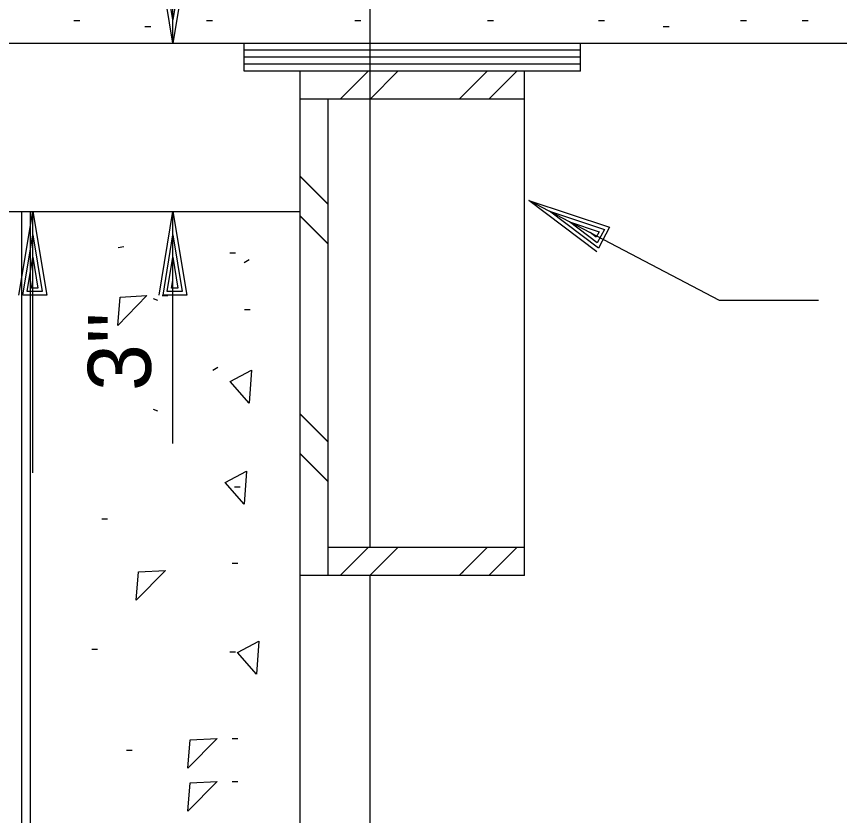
# Model space of a CAD drawing. Extents: x 22388.1 to 22405.7, y 22369.6 to 22390.4.
# Drawn here: x 22396.418 to 22397.03, y 22375.768 to 22376.362 of the extents above; entities that cross this region are included whole.
import ezdxf

# ---------------------------------------------------------------- set-up
doc = ezdxf.new("R2010")
doc.units = 0
for name, color, linetype in [('Level 1', 7, 'Continuous'), ('Level 2', 7, 'Continuous'), ('Level 44', 7, 'Continuous'), ('Level 50', 7, 'Continuous'), ('Level 7', 7, 'Continuous')]:
    doc.layers.add(name, color=color, linetype=linetype)

msp = doc.modelspace()

# ---------------------------------------------------------------- linework, layer by layer
at = {"layer": 'Level 1'}
for p, q in [((22396.53393, 22376.3425), (22396.53393, 22376.48702)), ((22396.837, 22376.33729), (22396.587, 22376.33729)), ((22396.837, 22376.33208), (22396.587, 22376.33208)), ((22396.837, 22376.32687), (22396.587, 22376.32687)), ((22396.62867, 22375.94666), (22396.62867, 22376.32166)), ((22396.65843, 22376.30083), (22396.67923, 22376.32166)), ((22396.68052, 22376.30083), (22396.70132, 22376.32166)), ((22396.74681, 22376.30083), (22396.76761, 22376.32166)), ((22396.76889, 22376.30083), (22396.78969, 22376.32166)), ((22396.6495, 22376.22286), (22396.62867, 22376.24369)), ((22396.64952, 22376.22259), (22396.62868, 22376.24342)), ((22396.42977, 22376.02321), (22396.42977, 22376.2175)), ((22396.53393, 22376.04496), (22396.53393, 22376.2175)), ((22396.6495, 22376.1934), (22396.62867, 22376.21423)), ((22396.64952, 22376.19313), (22396.62868, 22376.21397)), ((22396.6495, 22376.04609), (22396.62867, 22376.06692)), ((22396.64952, 22376.04582), (22396.62868, 22376.06665)), ((22396.6495, 22376.01663), (22396.62867, 22376.03746)), ((22396.64952, 22376.01636), (22396.62868, 22376.03719)), ((22396.65841, 22375.94666), (22396.67923, 22375.9675)), ((22396.65841, 22375.94666), (22396.67923, 22375.9675)), ((22396.6805, 22375.94666), (22396.70133, 22375.9675)), ((22396.6805, 22375.94666), (22396.70133, 22375.9675)), ((22396.74679, 22375.94666), (22396.76761, 22375.9675)), ((22396.76888, 22375.94666), (22396.7897, 22375.9675)), ((22396.74679, 22375.94666), (22396.74994, 22375.94982))]:
    msp.add_line(p, q, dxfattribs=at)
at = {"layer": 'Level 2'}
for p, q in [((22396.53393, 22376.35983), (22396.53393, 22376.35983)), ((22395.45158, 22376.3425), (22397.20637, 22376.3425)), ((22396.53393, 22376.3425), (22396.53393, 22376.3425)), ((22396.587, 22376.32166), (22396.587, 22376.3425)), ((22396.837, 22376.32166), (22396.837, 22376.3425)), ((22396.837, 22376.32166), (22396.587, 22376.32166)), ((22396.79534, 22375.94666), (22396.79534, 22376.32166)), ((22396.79534, 22376.30083), (22396.62867, 22376.30083)), ((22396.6495, 22375.94666), (22396.6495, 22376.30083)), ((22396.62867, 22375.94666), (22396.62867, 22376.2749)), ((22396.6495, 22375.94666), (22396.6495, 22376.2749)), ((22396.79871, 22376.22564), (22396.79871, 22376.22564)), ((22396.42169, 22375.10456), (22396.42169, 22376.2175)), ((22396.42814, 22375.10456), (22396.42814, 22376.2175)), ((22396.42977, 22376.2175), (22396.42977, 22376.2175)), ((22396.53393, 22376.2175), (22396.53393, 22376.2175)), ((22396.81406, 22376.21758), (22396.81406, 22376.21758)), ((22396.42977, 22376.20016), (22396.42977, 22376.20016)), ((22396.53393, 22376.20016), (22396.53393, 22376.20016)), ((22396.79534, 22375.9675), (22396.6495, 22375.9675)), ((22396.74973, 22375.9675), (22396.6495, 22375.9675)), ((22396.79534, 22375.94666), (22396.62867, 22375.94666)), ((22396.74997, 22375.94666), (22396.62867, 22375.94666))]:
    msp.add_line(p, q, dxfattribs=at)
for points in [[(22396.54427, 22376.40483), (22396.53393, 22376.3425), (22396.5236, 22376.40483), (22396.54127, 22376.40483), (22396.53393, 22376.35983), (22396.52693, 22376.40216), (22396.53827, 22376.40216), (22396.53393, 22376.3765), (22396.53027, 22376.3995), (22396.53493, 22376.3995), (22396.53393, 22376.39383)], [(22397.01395, 22376.15127), (22396.94032, 22376.15127), (22396.79871, 22376.22564)], [(22396.84909, 22376.18751), (22396.79871, 22376.22564), (22396.8587, 22376.20581), (22396.85048, 22376.19016), (22396.81406, 22376.21758), (22396.8548, 22376.20409), (22396.84953, 22376.19406), (22396.82882, 22376.20983), (22396.85088, 22376.20238), (22396.84871, 22376.19826), (22396.84416, 22376.20178)], [(22396.41943, 22376.15516), (22396.42977, 22376.2175), (22396.4401, 22376.15516), (22396.42243, 22376.15516), (22396.42977, 22376.20016), (22396.43677, 22376.15783), (22396.42543, 22376.15783), (22396.42977, 22376.1835), (22396.43343, 22376.1605), (22396.42877, 22376.1605), (22396.42977, 22376.16616)], [(22396.5236, 22376.15516), (22396.53393, 22376.2175), (22396.54427, 22376.15516), (22396.5266, 22376.15516), (22396.53393, 22376.20016), (22396.54093, 22376.15783), (22396.5296, 22376.15783), (22396.53393, 22376.1835), (22396.5376, 22376.1605), (22396.53293, 22376.1605), (22396.53393, 22376.16616)]]:
    msp.add_lwpolyline(points, dxfattribs=at)
at = {"layer": 'Level 44'}
for p, q in [((22396.46033, 22376.35932), (22396.46483, 22376.35932)), ((22396.55899, 22376.35933), (22396.56349, 22376.35933)), ((22396.66912, 22376.35933), (22396.67362, 22376.35933)), ((22396.76779, 22376.35932), (22396.77229, 22376.35932)), ((22396.85038, 22376.35932), (22396.85488, 22376.35932)), ((22396.95593, 22376.35933), (22396.96043, 22376.35933)), ((22397.00181, 22376.35934), (22397.00631, 22376.35934)), ((22396.5131, 22376.35502), (22396.5176, 22376.35502)), ((22396.89856, 22376.35502), (22396.90306, 22376.35502)), ((22396.49317, 22376.19058), (22396.4975, 22376.19133)), ((22396.57617, 22376.18671), (22396.58042, 22376.18671)), ((22396.58698, 22376.17954), (22396.59073, 22376.18179)), ((22396.51934, 22376.15283), (22396.52259, 22376.15158)), ((22396.52592, 22376.15488), (22396.53017, 22376.15488)), ((22396.58715, 22376.1446), (22396.5914, 22376.1446)), ((22396.49317, 22376.10558), (22396.4975, 22376.10633)), ((22396.56352, 22376.09952), (22396.56727, 22376.10177)), ((22396.51934, 22376.07055), (22396.52259, 22376.0693)), ((22396.57983, 22376.01276), (22396.58408, 22376.01276)), ((22396.48102, 22375.98896), (22396.48527, 22375.98896)), ((22396.578, 22375.956), (22396.58225, 22375.956)), ((22396.4737, 22375.89191), (22396.47795, 22375.89191)), ((22396.57617, 22375.89007), (22396.58042, 22375.89007)), ((22396.578, 22375.82558), (22396.58225, 22375.82558)), ((22396.49932, 22375.81683), (22396.50357, 22375.81683)), ((22396.578, 22375.79369), (22396.58225, 22375.79369))]:
    msp.add_line(p, q, dxfattribs=at)
for points in [[(22396.49467, 22376.1538), (22396.51467, 22376.15488), (22396.493, 22376.13272)], [(22396.59066, 22376.07494), (22396.57641, 22376.09094), (22396.59232, 22376.09944)], [(22396.58699, 22375.99987), (22396.57274, 22376.01587), (22396.58866, 22376.02437)], [(22396.50833, 22375.94942), (22396.52833, 22375.9505), (22396.50666, 22375.92834)], [(22396.59615, 22375.87353), (22396.5819, 22375.88953), (22396.59781, 22375.89803)], [(22396.54675, 22375.8245), (22396.56675, 22375.82558), (22396.54509, 22375.80341)], [(22396.54675, 22375.79261), (22396.56675, 22375.79369), (22396.54509, 22375.77153)]]:
    msp.add_lwpolyline(points, close=True, dxfattribs=at)
at = {"layer": 'Level 7'}
for p, q in [((22396.68075, 22376.2175), (22396.68075, 22378.49041)), ((22396.62867, 22376.2175), (22396.62867, 22376.32166)), ((22396.62867, 22374.6326), (22396.62867, 22376.2749)), ((22396.68075, 22375.9675), (22396.68075, 22376.2749)), ((22396.12866, 22376.2175), (22396.62867, 22376.2175)), ((22396.12866, 22376.2175), (22396.62867, 22376.2175)), ((22396.68075, 22375.19346), (22396.68075, 22375.94666))]:
    msp.add_line(p, q, dxfattribs=at)

# ---------------------------------------------------------------- texts
at = {"layer": 'Level 50'}
msp.add_text("3''", height=0.046875, rotation=90, dxfattribs=at).set_placement((22396.51757, 22376.08393))

doc.saveas('drawing.dxf')
